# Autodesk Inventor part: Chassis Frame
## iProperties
Shininess: 20.0
Angle Display Precision: 2
Document Length Units: 11269
Document Angle Units: 11279
Document Time Units: 11290
Document Mass Units: 11283
Document Length Units Precision: 3
Document Angle Units Precision: 2
Compacted: True
Created: 2001-08
Part Number: Chassis Frame
Document SubType Name: Modeling
Designer: Martin Budgell
Density: 0.0
Volumn: 0.0
Area: 0.0
PropertySet Name: Model Information
Control State: 0
Master: False
Checked Out: False
Author: Martin Budgell
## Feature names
1. Sweep1
2. Extrusion1
3. Extrusion2
4. Extrusion3
5. Fillet3
6. Sweep2
7. Extrusion4
8. Fillet4
9. Extrusion5
10. Sweep4
11. Fillet5
12. Extrusion6
13. Fillet6
14. Extrusion7
15. Fillet7
16. Extrusion8
17. Fillet8
18. Extrusion9
19. Fillet9
20. Mirror1
21. Extrusion13
22. Fillet13
23. Sweep7
24. Extrusion14
25. Fillet14
26. Sweep8
27. Fillet15
28. Fillet16
29. Extrusion15
30. Extrusion16
31. Extrusion17
32. Extrusion18
33. Extrusion19
34. Fillet17
35. Extrusion20
36. Extrusion21
37. Fillet18
38. Fillet19
39. Extrusion22
40. Extrusion23
41. Hole3
42. Extrusion24
43. Extrusion25
44. Fillet20
45. Hole4
46. Fillet22
47. Extrusion26
48. Extrusion27
49. Extrusion28
50. Fillet24
51. Fillet25
52. Mirror2
53. Fillet26
54. Hole5
55. Extrusion29
56. Mirror4
57. Fillet28
58. Fillet29
59. Extrusion32
60. Extrusion33
61. Fillet31
62. Extrusion34
63. Fillet32
64. Hole6
65. Extrusion35
66. Fillet33
67. Extrusion36
68. Mirror6
69. Fillet34
70. Fillet35
71. Hole7
72. Hole8
73. Hole9
74. Extrusion37
75. Fillet36
76. Fillet37
77. Mirror7
78. Fillet38
79. Hole10
80. Extrusion38
81. Extrusion39
82. Fillet40
83. Mirror8
84. Fillet41
85. Extrusion40
86. Fillet42
87. Extrusion41
88. Extrusion42
89. Extrusion43
90. Extrusion44
91. Fillet43
92. Chamfer2
93. Chamfer3
94. Fillet44
95. Fillet46
96. Fillet47
97. Extrusion45
98. Extrusion46
99. Extrusion47
100. Extrusion48
101. Fillet53
102. Fillet54
103. Fillet55
104. Fillet56
105. Fillet57
106. Fillet58
107. Hole11
108. Extrusion49
109. Fillet59
110. Extrusion50
111. Extrusion51
112. Extrusion52
113. Hole12
